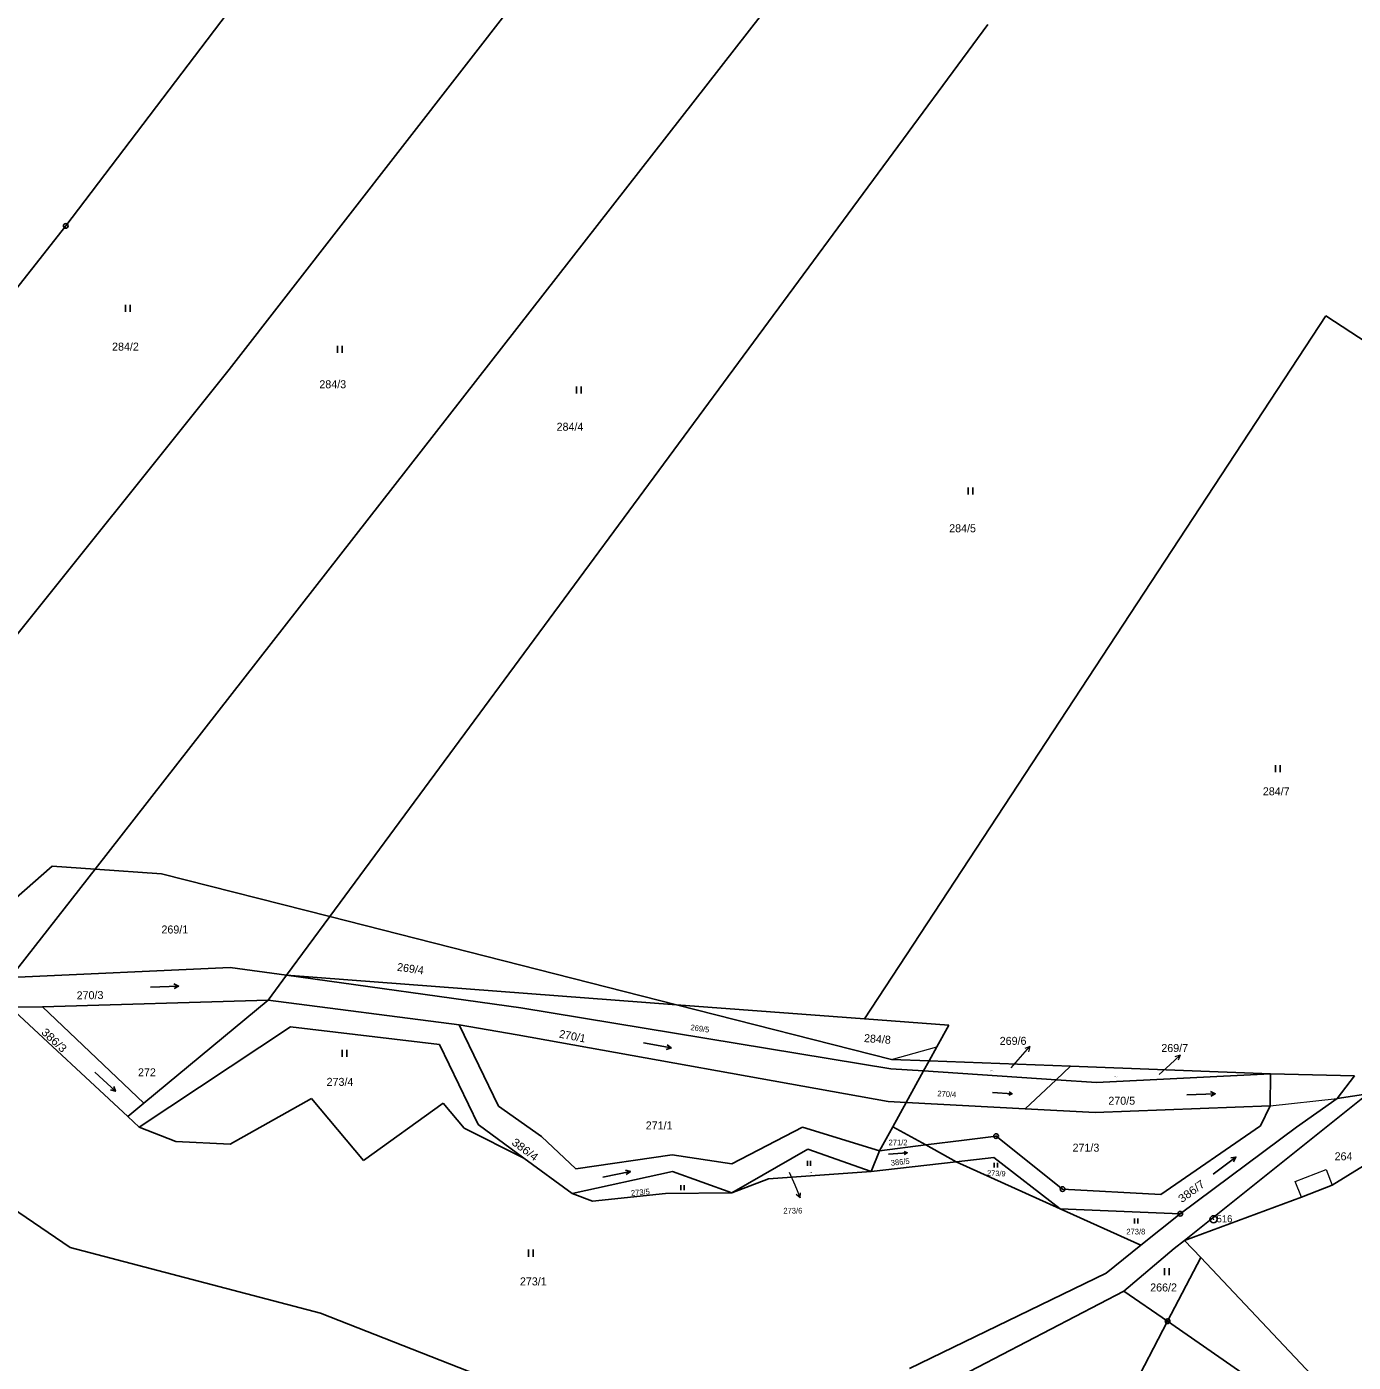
# Model space of a CAD drawing. Extents: x -504006 to -501322, y -1128098 to -1124665.
# Drawn here: x -503112.2 to -502830.4, y -1127108.2 to -1126824.4 of the extents above; entities that cross this region are included whole.
import ezdxf
from ezdxf.enums import TextEntityAlignment as Align

# ---------------------------------------------------------------- set-up
doc = ezdxf.new("R2010")
doc.units = 0
doc.header["$LTSCALE"] = 0.68
for name, color, linetype, lineweight in [('1', 7, 'Continuous', 25), ('3', 7, 'Continuous', 25), ('4', 7, 'Continuous', 13), ('7', 7, 'Continuous', 13), ('8', 7, 'Continuous', 25)]:
    doc.layers.add(name, color=color, linetype=linetype, lineweight=lineweight)
doc.layers.add('2', color=7, linetype='Continuous')

msp = doc.modelspace()

# ---------------------------------------------------------------- linework, layer by layer
at = {"layer": '1'}
for p, q in [((-503018.97, -1126754.86), (-503103.89, -1126866.73)), ((-502971.93, -1126772), (-503069.17, -1126897.27)), ((-502937.59, -1126798.13), (-503097.68, -1127003.42)), ((-503047.81, -1127013.5), (-502908.02, -1126823.96)), ((-503103.89, -1126866.73), (-503208.43, -1126998.55)), ((-502934.2, -1127035.26), (-502836.17, -1126885.85)), ((-502836.17, -1126885.85), (-502791.71, -1126915.01)), ((-503069.17, -1126897.27), (-503158.93, -1127009.27)), ((-503106.78, -1127002.78), (-503119.41, -1127013.89)), ((-503097.68, -1127003.42), (-503115.63, -1127026.44)), ((-503097.68, -1127003.42), (-503106.78, -1127002.78)), ((-503083.54, -1127004.42), (-503097.68, -1127003.42)), ((-503083.54, -1127004.42), (-503047.81, -1127013.5)), ((-503056.99, -1127025.96), (-503047.81, -1127013.5)), ((-503047.81, -1127013.5), (-502974.17, -1127032.23)), ((-503068.99, -1127024.29), (-503115.63, -1127026.44)), ((-503056.99, -1127025.96), (-503068.99, -1127024.29)), ((-503060.88, -1127031.23), (-503056.99, -1127025.96)), ((-502974.17, -1127032.23), (-503056.99, -1127025.96)), ((-503007.21, -1127032.87), (-503056.99, -1127025.96)), ((-503108.87, -1127032.68), (-503115.73, -1127032.72)), ((-503115.73, -1127032.72), (-503090.75, -1127055.99)), ((-503060.88, -1127031.23), (-503108.87, -1127032.68)), ((-503087.29, -1127053.12), (-503108.87, -1127032.68)), ((-503060.88, -1127031.23), (-503087.29, -1127053.12)), ((-503020.32, -1127036.49), (-503060.88, -1127031.23)), ((-502928.64, -1127045.84), (-503007.21, -1127032.87)), ((-502974.17, -1127032.23), (-502928.49, -1127043.84)), ((-502974.17, -1127032.23), (-502934.2, -1127035.26)), ((-502934.2, -1127035.26), (-502916.31, -1127036.61)), ((-503088.31, -1127058.27), (-503056.17, -1127036.91)), ((-503056.17, -1127036.91), (-503024.52, -1127040.68)), ((-503011.96, -1127053.8), (-503020.32, -1127036.49)), ((-503008.01, -1127038.61), (-503020.32, -1127036.49)), ((-502929.16, -1127052.8), (-503008.01, -1127038.61)), ((-502916.31, -1127036.61), (-502918.84, -1127041.18)), ((-503024.52, -1127040.68), (-503016.26, -1127057.72)), ((-502918.84, -1127041.18), (-502920.48, -1127044.15)), ((-502920.48, -1127044.15), (-502928.49, -1127043.84)), ((-502920.48, -1127044.15), (-502921.67, -1127046.3)), ((-502890.46, -1127045.29), (-502920.48, -1127044.15)), ((-502921.67, -1127046.3), (-502928.64, -1127045.84)), ((-502921.67, -1127046.3), (-502925.36, -1127053)), ((-502893.52, -1127048.18), (-502921.67, -1127046.3)), ((-502893.52, -1127048.18), (-502890.46, -1127045.29)), ((-502847.96, -1127046.92), (-502890.46, -1127045.29)), ((-502847.96, -1127046.92), (-502884.89, -1127048.75)), ((-502847.96, -1127046.92), (-502848.01, -1127053.75)), ((-502830.12, -1127047.35), (-502847.96, -1127046.92)), ((-502833.8, -1127052.17), (-502830.12, -1127047.35)), ((-502900.07, -1127054.33), (-502893.52, -1127048.18)), ((-502884.89, -1127048.75), (-502893.52, -1127048.18)), ((-503087.29, -1127053.12), (-503090.75, -1127055.99)), ((-503068.97, -1127061.89), (-503051.7, -1127052.18)), ((-503051.7, -1127052.18), (-503040.62, -1127065.33)), ((-503040.62, -1127065.33), (-503023.72, -1127053.13)), ((-503023.72, -1127053.13), (-503019.26, -1127058.46)), ((-502925.36, -1127053), (-502929.16, -1127052.8)), ((-502900.07, -1127054.33), (-502925.36, -1127053)), ((-502866.23, -1127082.3), (-502827.25, -1127051.17)), ((-502842.41, -1127058.24), (-502833.8, -1127052.17)), ((-502833.8, -1127052.17), (-502827.25, -1127051.17)), ((-503090.75, -1127055.99), (-503088.31, -1127058.27)), ((-503002.81, -1127060.25), (-503011.96, -1127053.8)), ((-502885.22, -1127055.11), (-502900.07, -1127054.33)), ((-502848.01, -1127053.75), (-502885.22, -1127055.11)), ((-502848.01, -1127053.75), (-502850.05, -1127057.94)), ((-503088.31, -1127058.27), (-503080.53, -1127061.29)), ((-503019.26, -1127058.46), (-503006.58, -1127064.81)), ((-503016.26, -1127057.72), (-503006.58, -1127064.81)), ((-502947.37, -1127058.22), (-502962.42, -1127066.02)), ((-502931.04, -1127063.28), (-502947.37, -1127058.22)), ((-502928.22, -1127058.17), (-502921.21, -1127062.04)), ((-502850.05, -1127057.94), (-502871.25, -1127072.57)), ((-502867.14, -1127076.64), (-502842.41, -1127058.24)), ((-502815.24, -1127058.45), (-502834.86, -1127070.61)), ((-503080.53, -1127061.29), (-503068.97, -1127061.89)), ((-502995.56, -1127067.1), (-503002.81, -1127060.25)), ((-502921.21, -1127062.04), (-502913, -1127061)), ((-502906.26, -1127060.15), (-502913, -1127061)), ((-502892.14, -1127071.42), (-502906.26, -1127060.15)), ((-502975.04, -1127064.1), (-502995.56, -1127067.1)), ((-502962.42, -1127066.02), (-502975.04, -1127064.1)), ((-502962.38, -1127072.22), (-502946.28, -1127062.95)), ((-502946.28, -1127062.95), (-502932.82, -1127067.64)), ((-502932.82, -1127067.64), (-502931.04, -1127063.28)), ((-502931.04, -1127063.28), (-502921.21, -1127062.04)), ((-502921.21, -1127062.04), (-502914.73, -1127065.61)), ((-502914.73, -1127065.61), (-502906.75, -1127064.71)), ((-502906.75, -1127064.71), (-502892.63, -1127075.58)), ((-503006.58, -1127064.81), (-502996.33, -1127072.34)), ((-502932.82, -1127067.64), (-502927.21, -1127067.01)), ((-502927.21, -1127067.01), (-502914.73, -1127065.61)), ((-502914.73, -1127065.61), (-502892.63, -1127075.58)), ((-502996.33, -1127072.34), (-502974.98, -1127067.7)), ((-502974.98, -1127067.7), (-502962.38, -1127072.22)), ((-502962.38, -1127072.22), (-502954.59, -1127069.25)), ((-502954.59, -1127069.25), (-502932.82, -1127067.64)), ((-503102.95, -1127083.84), (-503120.62, -1127071.82)), ((-502996.33, -1127072.34), (-502991.97, -1127073.95)), ((-502991.97, -1127073.95), (-502976.47, -1127072.36)), ((-502976.47, -1127072.36), (-502962.38, -1127072.22)), ((-502871.25, -1127072.57), (-502892.14, -1127071.42)), ((-502841.38, -1127073.13), (-502866.23, -1127082.3)), ((-502834.86, -1127070.61), (-502841.38, -1127073.13)), ((-502892.63, -1127075.58), (-502867.14, -1127076.64)), ((-502892.63, -1127075.58), (-502875.47, -1127083.32)), ((-502875.47, -1127083.32), (-502867.14, -1127076.64)), ((-503049.76, -1127097.8), (-503102.95, -1127083.84)), ((-502882.9, -1127089.27), (-502875.47, -1127083.32)), ((-502879.09, -1127093.07), (-502868.43, -1127084.04)), ((-502868.43, -1127084.04), (-502866.23, -1127082.3)), ((-502862.75, -1127085.98), (-502866.23, -1127082.3)), ((-502869.82, -1127099.5), (-502862.75, -1127085.98)), ((-502862.75, -1127085.98), (-502815.16, -1127136.34)), ((-502882.9, -1127089.27), (-502924.63, -1127109.54)), ((-502879.09, -1127093.07), (-502923.86, -1127116.38)), ((-502869.82, -1127099.5), (-502879.09, -1127093.07)), ((-502989.18, -1127121.53), (-503049.76, -1127097.8)), ((-502902.08, -1127161.18), (-502869.82, -1127099.5)), ((-502869.82, -1127099.5), (-502831.85, -1127125.83))]:
    msp.add_line(p, q, dxfattribs=at)
msp.add_lwpolyline([(-502931.04, -1127063.28), (-502928.22, -1127058.17), (-502925.36, -1127053)], dxfattribs=at)
at = {"layer": '3'}
for p, q in [((-503091.211, -1126885.03), (-503091.211, -1126883.53)), ((-503090.21, -1126885.03), (-503090.21, -1126883.53)), ((-503046.161, -1126893.7), (-503046.161, -1126892.2)), ((-503045.16, -1126893.7), (-503045.16, -1126892.2)), ((-502995.371, -1126902.36), (-502995.371, -1126900.86)), ((-502994.37, -1126902.36), (-502994.37, -1126900.86)), ((-502912.191, -1126923.84), (-502912.191, -1126922.34)), ((-502911.19, -1126923.84), (-502911.19, -1126922.34)), ((-502846.911, -1126982.85), (-502846.911, -1126981.35)), ((-502845.91, -1126982.85), (-502845.91, -1126981.35)), ((-503079.924, -1127028.263), (-503080.883, -1127028.798)), ((-503045.181, -1127043.32), (-503045.181, -1127041.82)), ((-503044.18, -1127043.32), (-503044.18, -1127041.82)), ((-502975.27, -1127041.402), (-502976.32, -1127041.726)), ((-503093.349, -1127050.624), (-503094.406, -1127050.324)), ((-502902.841, -1127051.137), (-502903.543, -1127051.451)), ((-502859.704, -1127051.163), (-502860.663, -1127051.698)), ((-502925.133, -1127063.685), (-502925.763, -1127064.066)), ((-502855.315, -1127064.601), (-502855.794, -1127065.59)), ((-502946.348, -1127066.46), (-502946.348, -1127065.41)), ((-502945.647, -1127066.46), (-502945.647, -1127065.41)), ((-502906.652, -1127066.85), (-502906.652, -1127065.845)), ((-502905.982, -1127066.85), (-502905.982, -1127065.845)), ((-502983.957, -1127067.641), (-502984.809, -1127068.335)), ((-502973.228, -1127071.66), (-502973.228, -1127070.61)), ((-502972.527, -1127071.66), (-502972.527, -1127070.61)), ((-502876.828, -1127078.7), (-502876.828, -1127077.65)), ((-502876.127, -1127078.7), (-502876.127, -1127077.65)), ((-503005.591, -1127085.78), (-503005.591, -1127084.28)), ((-503004.59, -1127085.78), (-503004.59, -1127084.28)), ((-502870.491, -1127089.71), (-502870.491, -1127088.21)), ((-502869.49, -1127089.71), (-502869.49, -1127088.21))]:
    msp.add_line(p, q, dxfattribs=at)
for points in [[(-503085.921, -1127028.473), (-503079.924, -1127028.263), (-503080.918, -1127027.796)], [(-502981.179, -1127040.36), (-502975.27, -1127041.402), (-502976.145, -1127040.739)], [(-503097.737, -1127046.532), (-503093.349, -1127050.624), (-503093.722, -1127049.591)], [(-502907.035, -1127050.917), (-502902.841, -1127051.137), (-502903.506, -1127050.75)], [(-502865.701, -1127051.373), (-502859.704, -1127051.163), (-502860.698, -1127050.696)], [(-502929.143, -1127063.965), (-502925.133, -1127063.685), (-502925.81, -1127063.395)], [(-502860.107, -1127068.212), (-502855.315, -1127064.601), (-502856.397, -1127064.789)], [(-502989.826, -1127068.889), (-502983.957, -1127067.641), (-502985.017, -1127067.354)]]:
    msp.add_lwpolyline(points, dxfattribs=at)
at = {"layer": '4'}
for p, q in [((-502928.49, -1127043.84), (-502918.84, -1127041.18)), ((-502848.01, -1127053.75), (-502833.8, -1127052.17)), ((-502842.68, -1127069.77), (-502836.16, -1127067.24)), ((-502836.16, -1127067.24), (-502834.86, -1127070.61)), ((-502841.38, -1127073.13), (-502842.68, -1127069.77))]:
    msp.add_line(p, q, dxfattribs=at)
at = {"layer": '7'}
for p, q in [((-502899.091, -1127041.125), (-502900.126, -1127041.552)), ((-502867.175, -1127042.973), (-502868.249, -1127043.29)), ((-502947.847, -1127073.292), (-502947.778, -1127072.175))]:
    msp.add_line(p, q, dxfattribs=at)
for points in [[(-502903.03, -1127045.66), (-502901.06, -1127043.39), (-502899.091, -1127041.125), (-502899.37, -1127042.209)], [(-502871.58, -1127047.06), (-502869.37, -1127045.02), (-502867.175, -1127042.973), (-502867.566, -1127044.023)], [(-502950.21, -1127067.78), (-502949.02, -1127070.53), (-502947.847, -1127073.292), (-502948.7, -1127072.566)]]:
    msp.add_lwpolyline(points, dxfattribs=at)
at = {"layer": '8'}
for centre, radius in [((-503103.89, -1126866.7299), 0.5), ((-503103.89, -1126866.7299), 0.0303), ((-502906.26, -1127060.1499), 0.5), ((-502906.26, -1127060.1499), 0.0303), ((-502892.14, -1127071.4199), 0.5), ((-502892.14, -1127071.4199), 0.0303), ((-502867.14, -1127076.6399), 0.5), ((-502867.14, -1127076.6399), 0.0303), ((-502860.06, -1127077.8098), 0.75), ((-502860.06, -1127077.8098), 0.03), ((-502869.82, -1127099.4999), 0.5), ((-502869.82, -1127099.4999), 0.0303)]:
    msp.add_circle(centre, radius, dxfattribs=at)

# ---------------------------------------------------------------- texts
at = {"layer": '2'}
for s, height, p in [('284/2', 1.7, (-503091.22, -1126893.235)), ('284/3', 1.7, (-503047.18, -1126901.235)), ('284/4', 1.7, (-502996.78, -1126910.265)), ('284/5', 1.7, (-502913.37, -1126931.835)), ('284/7', 1.7, (-502846.73, -1126987.735)), ('269/1', 1.7, (-503080.73, -1127017.095)), ('272', 1.7, (-503086.659, -1127047.445)), ('273/4', 1.7, (-503045.64, -1127049.475)), ('270/5', 1.7, (-502879.56, -1127053.485)), ('271/1', 1.7, (-502977.84, -1127058.735)), ('271/2', 1.2, (-502927.079, -1127062.1)), ('271/3', 1.7, (-502887.16, -1127063.455)), ('264', 1.7, (-502832.439, -1127065.295)), ('273/8', 1.2, (-502876.559, -1127081.05)), ('273/1', 1.7, (-503004.57, -1127091.875)), ('266/2', 1.7, (-502870.67, -1127093.165))]:
    msp.add_text(s, height=height, dxfattribs=at).set_placement(p, align=Align.CENTER)
for s, height, rotation, p in [('269/4', 1.7, 352, (-503030.7783, -1127025.3992)), ('270/3', 1.7, 1, (-503098.7348, -1127031.0544)), ('270/1', 1.7, 349, (-502996.4087, -1127039.7432)), ('269/5', 1.2, 352, (-502969.249, -1127037.8826)), ('284/8', 1.7, 356, (-502931.5183, -1127040.356)), ('269/6', 0.2, 357, (-502907.1292, -1127046.3996)), ('269/7', 0.2, 358, (-502880.8, -1127047.6197)), ('270/4', 1.2, 356, (-502916.7599, -1127051.8101)), ('386/5', 1.2, 6, (-502926.5662, -1127066.2444)), ('273/9', 1.139, 357, (-502906.2293, -1127068.6242)), ('273/6', 0.2, 4, (-502945.773, -1127068.0095)), ('273/5', 1.2, 5, (-502981.7773, -1127072.6762))]:
    msp.add_text(s, height=height, rotation=rotation, dxfattribs=at).set_placement(p, align=Align.CENTER)
at = {"layer": '2', "width": 1.1}
for s, rotation, p in [('386/3', 317, (-503106.9447, -1127040.4054)), ('386/4', 323, (-503006.8345, -1127063.6851)), ('386/7', 36, (-502864.2551, -1127072.5681))]:
    msp.add_text(s, height=1.7, rotation=rotation, dxfattribs=at).set_placement(p, align=Align.CENTER)
at = {"layer": '2'}
for s, height, p in [('269/6', 1.7, (-502905.48, -1127040.765)), ('269/7', 1.7, (-502871.15, -1127042.285)), ('273/6', 1.2, (-502951.44, -1127076.6))]:
    msp.add_text(s, height=height, dxfattribs=at).set_placement(p)
at = {"layer": '8'}
msp.add_text('516', height=1.5, dxfattribs=at).set_placement((-502856.059, -1127078.465), align=Align.RIGHT)

doc.saveas('drawing.dxf')
